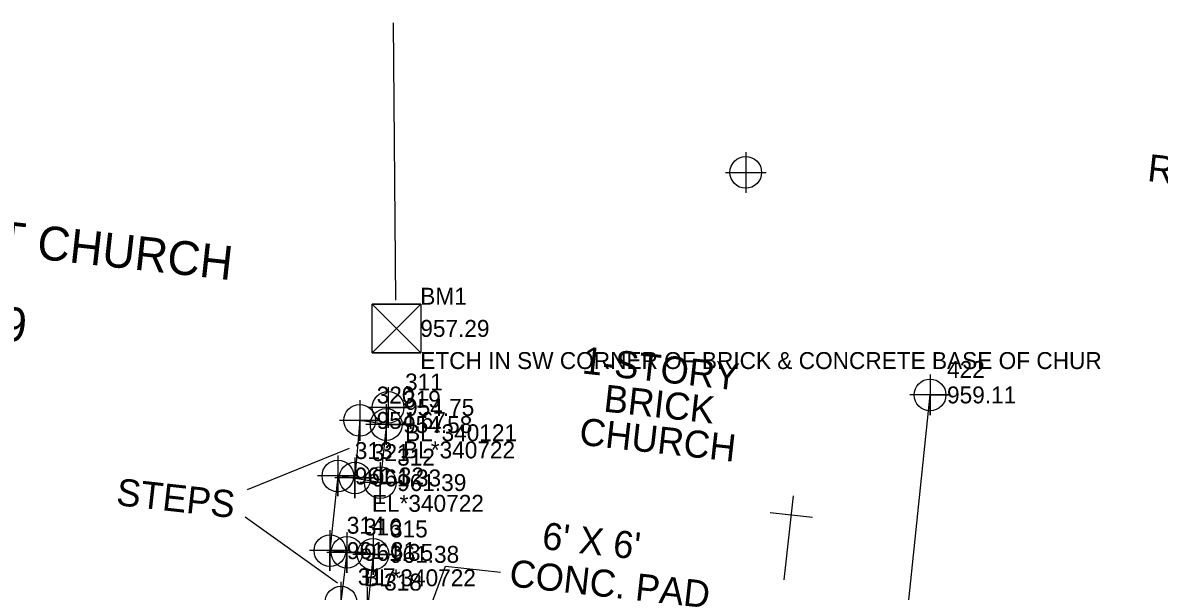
# Model space of a CAD drawing. Extents: x 1150279 to 1151282, y 654632 to 657999.
# Drawn here: x 1150909.2 to 1151077.1, y 657135.2 to 657219.1 of the extents above; entities that cross this region are included whole.
import ezdxf

# ---------------------------------------------------------------- set-up
doc = ezdxf.new("R2010")
doc.units = 0
for name, color, linetype in [('Cogo Default Point CELL', 7, 'Continuous'), ('CTL Bench Mark CELL', 7, 'Continuous'), ('CTL Bench Mark Cogo Comment', 7, 'Continuous'), ('CTL Bench Mark Cogo Elevation', 7, 'Continuous'), ('CTL Bench Mark Cogo Number', 7, 'Continuous'), ('CTL Bench Mark Leader', 7, 'Continuous'), ('Exist Building', 7, 'Continuous'), ('Exist Building Cogo Elevation', 7, 'Continuous'), ('Exist Building Cogo Number', 7, 'Continuous'), ('Exist Building Cogo Point CELL', 7, 'Continuous'), ('Exist Building Leader', 7, 'Continuous'), ('Exist Building Steps', 7, 'Continuous'), ('Exist Building Steps Cogo Comment', 7, 'Continuous'), ('Exist Building Steps Cogo Elevation', 7, 'Continuous'), ('Exist Building Steps Cogo Number', 7, 'Continuous'), ('Exist Building Steps Cogo Point CELL', 7, 'Continuous'), ('Exist Building Text', 7, 'Continuous'), ('Exist Other Culture Church or Cemetery CELL', 7, 'Continuous'), ('Exist Property Deed Book Text', 7, 'Continuous'), ('Exist Property Owner Text', 7, 'Continuous'), ('Exist Roads EOP Leader', 7, 'Continuous'), ('Exist Roads EOP Text', 7, 'Continuous'), ('Exist Utilities Power Pole Text', 7, 'Continuous')]:
    doc.layers.add(name, color=color, linetype=linetype)

msp = doc.modelspace()

# ---------------------------------------------------------------- linework, layer by layer
at = {"layer": 'Cogo Default Point CELL'}
for points in [[(1151016.01, 657199.99), (1151016.01, 657196.99)], [(1151013.01, 657196.99), (1151016.01, 657196.99)], [(1151016.01, 657196.99), (1151019.01, 657196.99)], [(1151016.01, 657196.99), (1151016.01, 657193.99)]]:
    msp.add_lwpolyline(points, dxfattribs=at)
msp.add_circle((1151016.01, 657196.99), 2.34, dxfattribs=at)
at = {"layer": 'CTL Bench Mark CELL'}
msp.add_line((1150964.42, 657173.96), (1150964.42, 657173.96), dxfattribs=at)
msp.add_lwpolyline([(1150960.82, 657177.55), (1150968.01, 657177.55), (1150968.01, 657170.36), (1150960.82, 657170.36)], close=True, dxfattribs=at)
for points in [[(1150968.01, 657177.55), (1150960.82, 657170.36), (1150964.42, 657173.95), (1150968.01, 657170.36), (1150960.82, 657177.55)], [(1150964.42, 657173.95), (1150968.01, 657177.55), (1150960.82, 657177.55), (1150964.42, 657173.95)], [(1150964.42, 657173.95), (1150960.82, 657170.36), (1150968.01, 657170.36), (1150964.42, 657173.95)]]:
    msp.add_lwpolyline(points, dxfattribs=at)
at = {"layer": 'CTL Bench Mark Leader'}
msp.add_line((1150964.33, 657178.12), (1150963.96, 657219.08), dxfattribs=at)
at = {"layer": 'Exist Building'}
msp.add_lwpolyline([(1150963.17, 657162.3), (1150962, 657151.2), (1150955.74, 657152.17), (1150954.56, 657141.15), (1150960.94, 657140.6), (1150959.8, 657129.69), (1151003.45, 657125.16), (1151002.47, 657115.2), (1151037.8, 657111.58), (1151043.24, 657164.14)], dxfattribs=at)
at = {"layer": 'Exist Building Cogo Point CELL'}
for points in [[(1151043.24, 657167.14), (1151043.24, 657161.14), (1151043.24, 657164.14), (1151046.24, 657164.14), (1151040.24, 657164.14)], [(1150963.17, 657165.3), (1150963.17, 657159.3), (1150963.17, 657162.3), (1150966.17, 657162.3), (1150960.17, 657162.3)], [(1150955.74, 657155.17), (1150955.74, 657149.17), (1150955.74, 657152.17), (1150958.74, 657152.17), (1150952.74, 657152.17)], [(1150962, 657154.2), (1150962, 657148.2), (1150962, 657151.2), (1150965, 657151.2), (1150959, 657151.2)], [(1150954.56, 657144.15), (1150954.56, 657138.15), (1150954.56, 657141.15), (1150957.56, 657141.15), (1150951.56, 657141.15)], [(1150960.94, 657143.6), (1150960.94, 657137.6), (1150960.94, 657140.6), (1150963.94, 657140.6), (1150957.94, 657140.6)]]:
    msp.add_lwpolyline(points, dxfattribs=at)
for centre in [(1151043.24, 657164.14), (1150963.17, 657162.3), (1150955.74, 657152.17), (1150962, 657151.2), (1150954.56, 657141.15), (1150960.94, 657140.6)]:
    msp.add_circle(centre, 2.34, dxfattribs=at)
at = {"layer": 'Exist Building Leader'}
for p, q in [((1150957.42, 657156.25), (1150942.32, 657150.13)), ((1150955.7, 657136.33), (1150942.03, 657146.11))]:
    msp.add_line(p, q, dxfattribs=at)
at = {"layer": 'Exist Building Steps'}
for points in [[(1150962.88, 657159.77), (1150958.98, 657160.37), (1150958.27, 657151.88)], [(1150957.09, 657140.89), (1150956.19, 657133.54), (1150960.08, 657132.75)]]:
    msp.add_lwpolyline(points, dxfattribs=at)
at = {"layer": 'Exist Building Steps Cogo Point CELL'}
for points in [[(1150958.98, 657163.37), (1150958.98, 657157.37), (1150958.98, 657160.37), (1150961.98, 657160.37), (1150955.98, 657160.37)], [(1150962.88, 657162.77), (1150962.88, 657156.77), (1150962.88, 657159.77), (1150965.88, 657159.77), (1150959.88, 657159.77)], [(1150958.27, 657154.88), (1150958.27, 657148.88), (1150958.27, 657151.88), (1150961.27, 657151.88), (1150955.27, 657151.88)], [(1150957.09, 657143.89), (1150957.09, 657137.89), (1150957.09, 657140.89), (1150960.09, 657140.89), (1150954.09, 657140.89)], [(1150956.19, 657136.54), (1150956.19, 657130.54), (1150956.19, 657133.54), (1150959.19, 657133.54), (1150953.19, 657133.54)], [(1150960.08, 657135.75), (1150960.08, 657129.75), (1150960.08, 657132.75), (1150963.08, 657132.75), (1150957.08, 657132.75)]]:
    msp.add_lwpolyline(points, dxfattribs=at)
for centre in [(1150958.98, 657160.37), (1150962.88, 657159.77), (1150958.27, 657151.88), (1150957.09, 657140.89), (1150956.19, 657133.54)]:
    msp.add_circle(centre, 2.34, dxfattribs=at)
at = {"layer": 'Exist Other Culture Church or Cemetery CELL'}
for p, q in [((1151021.68, 657136.83), (1151023.05, 657149.22)), ((1151019.63, 657146.78), (1151025.87, 657146.09)), ((1151022.37, 657143.04), (1151022.37, 657143.04))]:
    msp.add_line(p, q, dxfattribs=at)
at = {"layer": 'Exist Roads EOP Leader'}
msp.add_lwpolyline([(1150966.81, 657125.7), (1150971.62, 657138.86), (1150979.78, 657137.96)], dxfattribs=at)

# ---------------------------------------------------------------- texts
at = {"layer": 'CTL Bench Mark Cogo Comment'}
msp.add_text('ETCH IN SW CORNER OF BRICK & CONCRETE BASE OF CHUR', height=2.5, dxfattribs=at).set_placement((1150967.92, 657167.96))
at = {"layer": 'CTL Bench Mark Cogo Elevation'}
msp.add_text('957.29', height=2.5, dxfattribs=at).set_placement((1150967.92, 657172.71))
at = {"layer": 'CTL Bench Mark Cogo Number'}
msp.add_text('BM1', height=2.5, dxfattribs=at).set_placement((1150967.92, 657177.46))
at = {"layer": 'Exist Building Cogo Elevation'}
for s, p in [('959.11', (1151045.74, 657162.89)), ('954.75', (1150965.67, 657161.05)), ('BL*340121', (1150965.67, 657157.3)), ('961.32', (1150958.24, 657150.92)), ('961.39', (1150964.5, 657149.95)), ('961.31', (1150957.06, 657139.9)), ('961.38', (1150963.44, 657139.35))]:
    msp.add_text(s, height=2.5, dxfattribs=at).set_placement(p)
at = {"layer": 'Exist Building Cogo Number'}
for s, p in [('422', (1151045.74, 657166.64)), ('311', (1150965.67, 657164.8)), ('313', (1150958.24, 657154.67)), ('312', (1150964.5, 657153.7)), ('314', (1150957.06, 657143.65)), ('315', (1150963.44, 657143.1))]:
    msp.add_text(s, height=2.5, dxfattribs=at).set_placement(p)
at = {"layer": 'Exist Building Steps Cogo Comment'}
for s, p in [('BL*340722', (1150965.38, 657154.77)), ('EL*340722', (1150960.77, 657146.88)), ('BL*340722', (1150959.59, 657135.89))]:
    msp.add_text(s, height=2.5, dxfattribs=at).set_placement(p)
at = {"layer": 'Exist Building Steps Cogo Elevation'}
for s, p in [('954.67', (1150961.48, 657159.12)), ('954.58', (1150965.38, 657158.52)), ('961.33', (1150960.77, 657150.63)), ('961.35', (1150959.59, 657139.64))]:
    msp.add_text(s, height=2.5, dxfattribs=at).set_placement(p)
at = {"layer": 'Exist Building Steps Cogo Number'}
for s, p in [('320', (1150961.48, 657162.87)), ('319', (1150965.38, 657162.27)), ('321', (1150960.77, 657154.38)), ('316', (1150959.59, 657143.39)), ('317', (1150958.69, 657136.04)), ('318', (1150962.58, 657135.25))]:
    msp.add_text(s, height=2.5, dxfattribs=at).set_placement(p)
at = {"layer": 'Exist Building Text'}
for s, p in [('1-STORY', (1150991.71, 657167.33)), ('BRICK', (1150994.89, 657161.7)), ('CHURCH', (1150991.28, 657156.81)), ('STEPS', (1150922.88, 657147.88))]:
    msp.add_text(s, height=4, rotation=353.6867, dxfattribs=at).set_placement(p)
at = {"layer": 'Exist Property Deed Book Text'}
msp.add_text('DB 500 PG 419', height=5, rotation=353.6867, dxfattribs=at).set_placement((1150862.94, 657177.01))
at = {"layer": 'Exist Property Owner Text'}
msp.add_text('CANE CREEK BAPTIST CHURCH', height=5, rotation=353.6867, dxfattribs=at).set_placement((1150836.54, 657192.51))
at = {"layer": 'Exist Roads EOP Text'}
for s, p in [("6' X 6'", (1150985.78, 657141.4)), ('CONC. PAD', (1150980.94, 657135.9))]:
    msp.add_text(s, height=4, rotation=353.6867, dxfattribs=at).set_placement(p)
at = {"layer": 'Exist Utilities Power Pole Text'}
msp.add_text('REMCO', height=4, rotation=353.6867, dxfattribs=at).set_placement((1151075.23, 657195.73))

doc.saveas('drawing.dxf')
